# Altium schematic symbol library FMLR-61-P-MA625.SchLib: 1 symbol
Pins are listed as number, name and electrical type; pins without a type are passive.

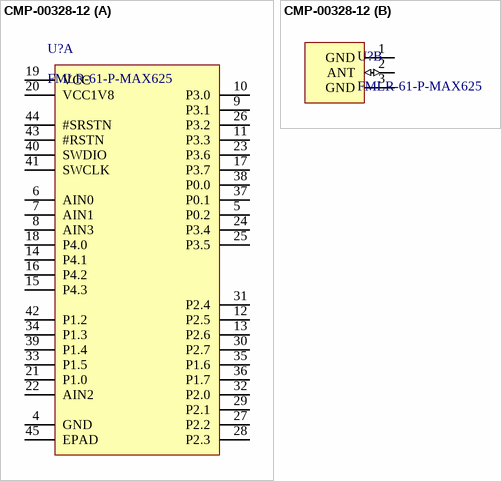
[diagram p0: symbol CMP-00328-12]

## CMP-00328-12
designator U?, comment FMLR-61-P-MAX625
868/915 MHz LoRa Module with SX1261 and MAX32625; Manufacturer: Miromico
footprint FMLR-6x-P-MAX62x-Footprint-1
part A pins: 4 GND (power), 5 P0.2, 6 AIN0, 7 AIN1, 8 AIN3, 9 P3.1, 10  P3.0, 11 P3.3, 12  P2.5, 13 P2.6, 14 P4.1, 15 P4.3, 16 P4.2, 17 P3.7, 18 P4.0, 19 VCC (power), 20 VCC1V8 (power), 21 P1.0, 22 AIN2, 23 P3.6, 24 P3.4, 25 P3.5, 26 P3.2, 27 P2.2, 28 P2.3, 29 P2.1, 30 P2.7, 31 P2.4, 32 P2.0, 33 P1.5, 34 P1.3, 35 P1.6, 36 P1.7, 37 P0.1, 38 P0.0, 39 P1.4, 40 SWDIO, 41 SWCLK, 42 P1.2, 43 #RSTN, 44 #SRSTN, 45 EPAD (power)
part B pins: 1 GND (power) "Serial Interface Data", 2 ANT (io) "Serial Interface Data", 3 GND (power) "Serial Interface Data"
